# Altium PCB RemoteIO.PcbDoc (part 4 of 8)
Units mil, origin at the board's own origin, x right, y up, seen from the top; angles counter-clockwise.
Board outline 7874.02 x 2362.2 mil, 6 copper layers (Top Layer, GND1, Layer 2, PWR, GND2, Bottom Layer), stack 60.956 mil thick; 655 components, 447 nets, 2607 pads, 1444 vias.
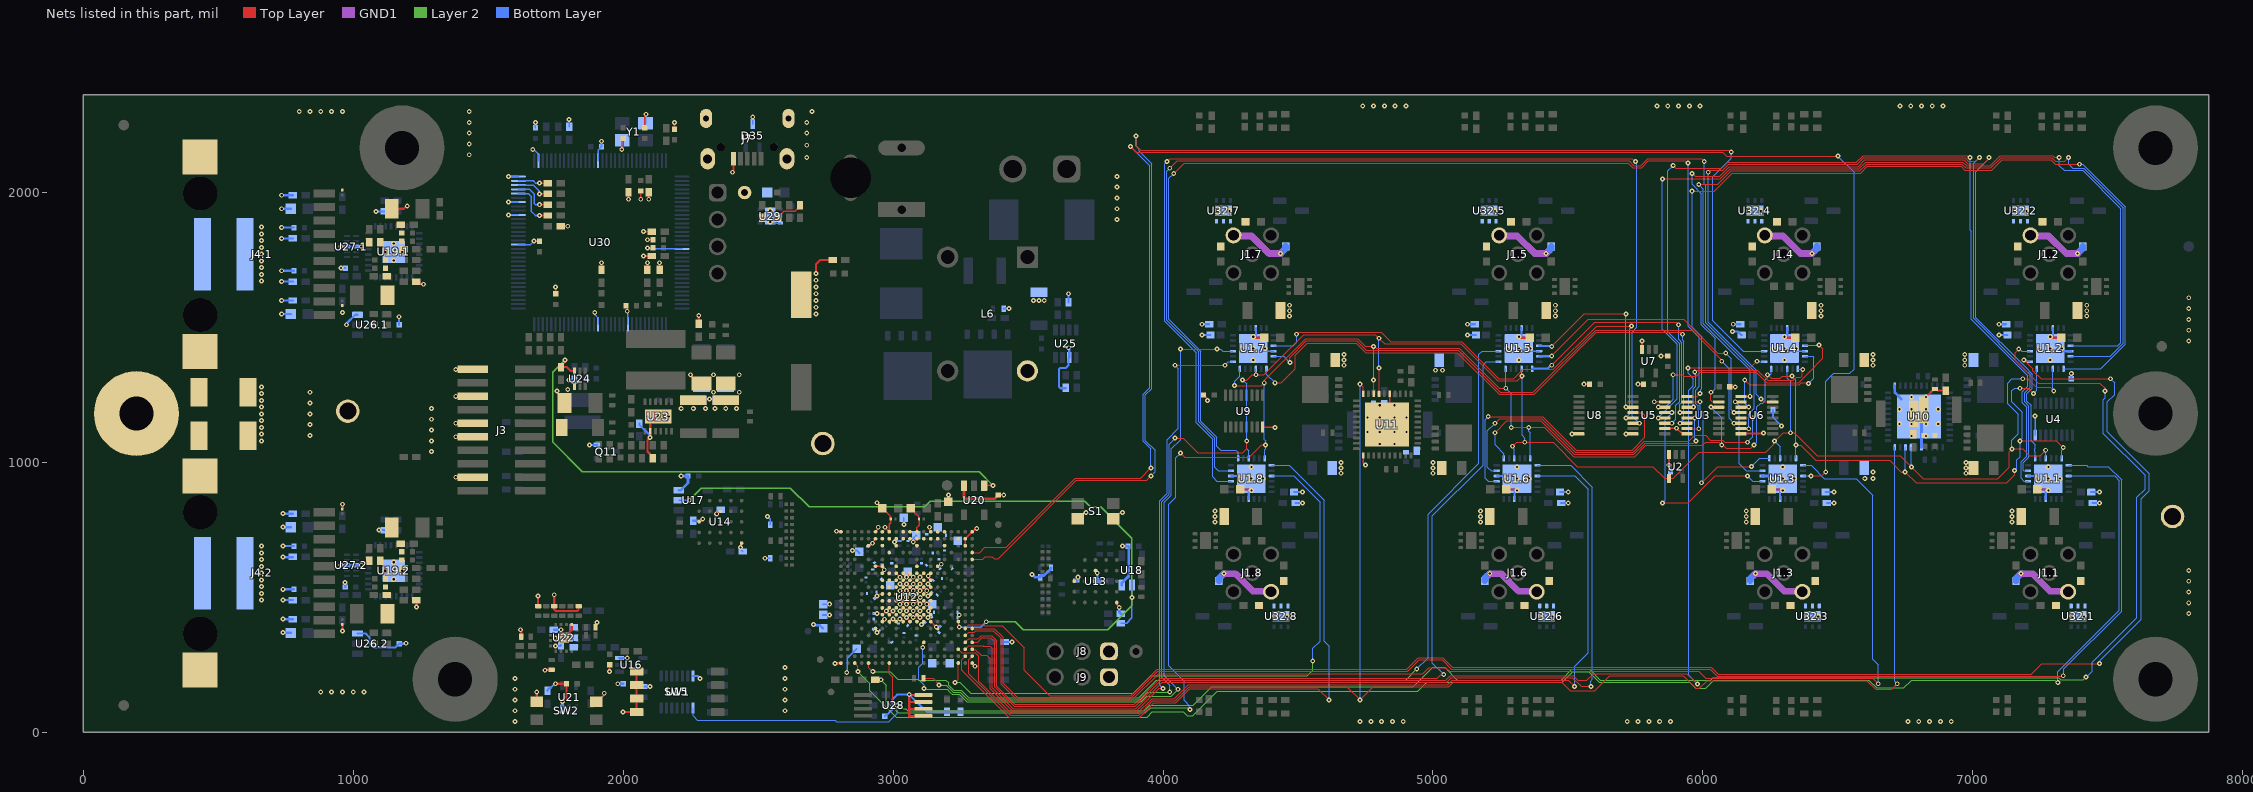
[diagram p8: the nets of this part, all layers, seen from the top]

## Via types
v1: diameter 18, hole 8, Top Layer to Bottom Layer, tented both sides, 1277 vias
v2: diameter 19.68, hole 7.87, Top Layer to Bottom Layer, tented both sides, 133 vias
v3: diameter 19.68, hole 7.87, Top Layer to Bottom Layer, 34 vias

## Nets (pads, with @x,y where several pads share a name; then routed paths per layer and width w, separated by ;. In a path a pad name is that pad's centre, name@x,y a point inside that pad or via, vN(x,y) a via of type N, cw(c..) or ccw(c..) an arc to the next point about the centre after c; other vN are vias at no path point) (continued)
\WARMRST: R113.2 U12.G3 U17.2 U18.2 | length 2932
  Top Layer w6: U12.G3@3241.93,410.43 3243.42,408.94 3243.42,391.58 v1(3245,390)
  Layer 2 w5: v1(2245,860) 2290,905 2620,905 2690,835 3117.73,835 3138.23,855.5 3709.5,855.5 3730,835 3770,835 3885,720 v1(3885,500) 3885,470 3795,380 3650,380 3649.5,379.5 3482.72,379.5 3452.22,410 v1(3345,410)
  Bottom Layer w5: U17.2@2205.87,860 v1(2245,860) ; v1(3245,390) 3325,390 v1(3345,410) ; R113.2@3843.62,405 3865,405 3885,425 v1(3885,500) U18.2@3885,545.87
CS1: U1.1.1 U12.F1 | length 5365.4
  Top Layer w4: U12.F1@3293.11,384.84 3375.16,384.84 3408,352 3408,181.63 3461.63,128 3883.25,128 3981.25,226 4906,226 4949,269 5033.63,269 5068.63,234 6027.87,234 6053.87,208 7333,208 v1(7335,210)
  Bottom Layer w4: v1(7335,210) 7337.53,212.53 7337.53,235.15 7551,448.63 7551,935.31 7501.31,985 7425.86,985 7421.65,989.21 U1.1.1@7355.3,989.21
CS2: U1.2.1 U12.F2 | length 6056.3
  Top Layer w4: U12.F2@3267.52,384.84 3280.72,398.04 3335.74,398.04 3338.79,395 3405,395 3486,314 3486,230.64 3580.64,136 3879.94,136 3977.94,234 4902.69,234 4945.69,277 5036.94,277 5071.94,242 6031.18,242 6057.18,216 7216,216 7255,255 v1(7470,255) ; v1(7189.04,1379.8) 7222.32,1346.52 7222.32,1340.6 7252.92,1310 v1(7510,1310)
  Bottom Layer w4: v1(7189.04,1379.8) 7192.83,1379.8 7196.91,1375.72 7208.91,1375.72 U1.2.1@7211.63,1372.99 ; v1(7470,255) 7471.63,256.63 7471.63,266.58 7624,418.95 7624,864.69 7654,894.69 7654,958.73 7499,1113.73 7499,1225.16 7525,1251.16 7525,1295 v1(7510,1310)
CS3: U1.3.1 U12.E2 | length 4681.6
  Top Layer w4: U12.E2@3267.52,359.25 3279.91,371.64 3301.64,371.64 3306.84,376.84 3371.84,376.84 3400,348.69 3400,178.31 3458.31,120 3886.57,120 3983.57,217 4962,217 4985,240 5047.53,240 5061.53,226 5984,226 6010,200 6630,200 v1(6650,180)
  Bottom Layer w4: U1.3.1@6371.04,989.21 6400.79,989.21 6450,940 6567.63,940 6630,877.63 6630,271.31 6650,251.31 v1(6650,180)
CS4: U1.4.1 U12.D1 | length 4484.5
  Top Layer w4: 3306,334.69 3294.14,334.69 U12.D1@3293.11,333.66 3312.82,333.66 3329.15,350 3362.37,350 3376,336.37 3376,168.37 3448.37,96 3896.51,96 3993.51,193 5048,193 5065,210 5520,210 5537,193 5570,193 5595,218 5941,218 5966,193 v1(5980,179) ; v1(5945,1350) 6175,1350 v1(6200,1375)
  Bottom Layer w4: v1(5945,1350) 5945,1330 5965,1310 5965,1285 5948,1268 5948,211 v1(5980,179) ; v1(6200,1375) 6201,1374 6226.38,1374 U1.4.1@6227.38,1372.99
CS5: U1.5.1 U12.D2 | length 3335.4
  Top Layer w4: U12.D2@3267.52,333.66 3279.91,346.05 3313.89,346.05 3325.84,358 3365.69,358 3384,339.69 3384,171.69 3451.69,104 3893.2,104 3990.2,201 5016.1,201 5028.44,213.34 5038.34,213.34 v1(5040,215)
  Bottom Layer w4: v1(5040,215) 4998.16,256.84 4998.16,801.84 5186,989.69 5186,1361 5197.99,1372.99 U1.5.1@5243.13,1372.99
CS6: U1.6.1 U12.C2 | length 3544.4
  Top Layer w4: U12.C2@3267.52,308.07 3279.91,320.46 3333.33,320.46 3333.79,320 3360,320 3368,312 3368,165.06 3445.06,88 3899.82,88 3996.82,185 5051.31,185 5068.31,202 5516.69,202 5548.69,170 v1(5585,170)
  Bottom Layer w4: U1.6.1@5386.79,989.21 5510.79,989.21 5591,909 5591,196 5585,190 v1(5585,170)
CS7: U1.7.1 U12.C1 | length 2359.3
  Top Layer w4: U12.C1@3294.98,309.94 U12.C1@3293.11,308.07 3294.98,306.2 3305.11,306.2 3326.31,285 3347.66,285 3360,272.66 3360,161.75 3441.75,80 3903.14,80 3986.14,163 v1(4000,163) ; v1(4045,1360) v1(4230,1360)
  Bottom Layer w4: v1(4000,163) 3988,175 3988,858 4015,885 4015,1085 4057,1127 4057,1348 v1(4045,1360) ; v1(4230,1360) 4230,1361.94 4241.05,1372.99 U1.7.1@4258.88,1372.99
CS8: U1.8.1 U12.B2 | length 2546
  Top Layer w4: U12.B2@3267.52,282.48 3255,269.96 3255,230 3425,60 3425.65,60 3429.65,56 3913.08,56 3966.08,109 4047.84,109 4099.84,161 4574,161 v1(4615,120)
  Bottom Layer w4: U1.8.1@4402.54,989.21 4468.41,989.21 4598,859.63 4598,337 4615,320 v1(4615,120)
DCDC_PG: R127.1 U20.1 U24.6 | length 2142.6
  Top Layer w6: R127.1@1770,1353.62 1770,1357.56 1785,1372.56 v1(1785,1380) ; U20.1@3337.4,914.13 3338.27,915 v1(3370,915)
  Top Layer w8: R127.1@1770,1353.62 1791.38,1353.62 1805.87,1339.13 U24.6@1820.32,1339.13
  Layer 2 w6: v1(1785,1380) 1739,1334 1739,1076 1849,966 3319,966 v1(3370,915)
DEBUG_ID4: R197.1 U30.63 | length 113
  Top Layer w6: v1(1690,2035) R197.1@1721.38,2035
  Bottom Layer w6: U30.63@1611.85,2043.35 1666.65,2043.35 1675,2035 v1(1690,2035)
DEBUG_ID5: R198.1 U30.62 | length 128.9
  Top Layer w6: v1(1690,1995) R198.1@1721.38,1995
  Bottom Layer w6: U30.62@1611.85,2027.6 1667.4,2027.6 1688.27,2006.73 1688.27,1996.73 v1(1690,1995)
DEBUG_ID6: R199.1 U30.61 | length 153.6
  Top Layer w6: v1(1690,1955) R199.1@1721.38,1955
  Bottom Layer w6: U30.61@1611.85,2011.85 1653.15,2011.85 1670,1995 1670,1960 1675,1955 v1(1690,1955)
DEBUG_ID7: R200.1 U30.60 | length 175.3
  Top Layer w6: v1(1690,1915) R200.1@1721.38,1915
  Bottom Layer w6: U30.60@1611.85,1996.1 1648.9,1996.1 1660,1985 1660,1930 1675,1915 v1(1690,1915)
DIN: R39.2 U1.1.24 U1.2.24 U1.3.24 U1.4.24 U1.5.24 U1.6.24 U1.7.24 U1.8.24 U3.14 U10.8 U11.8 | length 8243.9
  Top Layer w4: v1(4065,1035) 4080,1020 4320,1020 4365,1065 v1(4380,1065) ; v1(4265,1285) 4363.79,1285 4373.79,1295 v1(4375,1295) 4376.66,1296.66 4376.66,1306.56 4528.1,1458 4722,1458 4750,1430 v1(4780,1430) 4782.34,1430 4789.34,1423 5097,1423 5245,1275 v1(5270,1275) ; v1(4780,1305) 4780.39,1304.61 4780.39,1254.57 U11.8@4780.79,1254.17 ; v1(5290,1130) v1(5355,1130) 5412.63,1130 5520.84,1021.78 5748.1,1021.78 5789.31,1063 5998,1063 6010,1075 6058.79,1075 v1@6068.79,1065 ; v1(6070,1065) 6073.79,1065 6085.79,1053 6178,1053 v1(6190,1065) ; v1(6240,1325) 6252.8,1312.2 6287.2,1312.2 6295,1320 v1(6330,1320) ; v1(6345,1065) 6346.26,1063.74 6362.42,1063.74 6418.16,1008 6692,1008 6735.61,964.39 v1(6749.39,964.39) 6789.79,924 7125.21,924 7155,953.79 v1(7155,970) ; v1(7175,1080) 7310,1080 v1(7335,1055) ; v1(7175,1275) 7205,1275 v1(7225,1255)
  Top Layer w8: R39.2@2933.62,195 v1(2955,195) ; v1(6030,1205) 6030.24,1204.76 6058.82,1204.76 U3.14@6059.06,1204.53
  Layer 2 w4: v1(2955,195) 2975,175 2975,115.26 3018.26,72 3934.37,72 3954.37,92 4090.66,92 4097.66,85 v1(4100,85)
  Bottom Layer w4: v1(4065,1035) 4047,1017 4047,871.75 4021,845.75 4021,246.53 4078.34,189.18 4078.34,173.34 4078,173 4078,118.79 4097.32,99.47 4097.32,87.68 v1(4100,85) ; v1(4265,1285) 4265,1300 4284.96,1319.96 U1.7.24@4284.96,1346.91 ; v1(4375,1295) 4375,1085 4380.15,1079.85 v1@4380.15,1065 ; U1.8.24@4376.46,1015.3 4376.46,1046.46 4380,1050 v1(4380,1065) ; v1(4780,1305) v1(4780,1430) ; U1.5.24@5269.21,1346.91 5269.61,1346.52 5269.61,1275.39 v1(5270,1275) 5290,1255 v1(5290,1130) ; v1(5355,1130) 5355,1115 5360.71,1109.29 U1.6.24@5360.71,1015.3 ; v1(6030,1205) 6070,1165 v1(6070,1065) ; v1(6190,1065) 6200,1075 6200,1206.21 6213.79,1220 6221.21,1220 6232,1230.79 6232,1307 v1@6245,1320 ; v1(6240,1325) v1@6245,1320 ; U1.4.24@6253.46,1346.91 6253.46,1328.46 v1@6245,1320 ; v1(6330,1320) 6345,1305 v1(6345,1065) U1.3.24@6344.96,1015.3 ; v1(6749.39,964.39) 6750.09,965.09 6750.09,1055.13 U10.8@6750.79,1055.83 ; v1(7155,970) 7155,971.06 7163.29,979.34 7163.29,1009.35 7175,1021.06 v1(7175,1080) 7184,1089 7184,1186 7145,1225 7145,1265 7155,1275 v1(7175,1275) ; v1(7225,1255) 7237.72,1267.72 U1.2.24@7237.72,1346.91 ; U1.1.24@7329.21,1015.3 7329.21,1045.42 7335,1051.21 v1(7335,1055)
DIO_EN1: U1.1.19 U3.15 | length 3299.3
  Top Layer w4: v1(5960,2070) 5961.21,2070 5971.21,2060 6062.63,2060 6098.63,2096 6574.94,2096 6599.94,2121 6966.47,2121 6980.47,2107 7040.79,2107 v1@7061.01,2127.22 ; v1(6030,1260) 6030,1230 6034.73,1225.27 6058,1225.27 U3.15@6059.06,1224.21
  Bottom Layer w4: v1(5960,2070) 5960,2030 5994,1996 5994,1510.9 6045,1459.9 6045,1272.5 6032.5,1260 v1(6030,1260) ; v1@7060.81,2127.02 7011,2077.21 7011,1536.63 7191.63,1356 7220,1327.63 7220,1275 7200,1255 7200,1227.63 7216,1211.63 7216,1079.82 7230.47,1065.34 7230.47,1051.69 7230,1051.21 7230,1038.79 7230.79,1038 U1.1.19@7230.79,1015.3
  other v1: 7060,2130
DIO_EN2: U1.2.19 U3.1 | length 3332.6
  Top Layer w4: U3.1@5940.94,1243.9 5977.06,1243.9 5988.16,1255 v1(5990,1255) ; v1(5960,2005) 6041.57,2005 6108.57,2072 6584.88,2072 6609.88,2097 6956.53,2097 6970.53,2083 7070.63,2083 7108.63,2121 7289,2121 7305,2105 v1(7395,2105)
  Bottom Layer w4: v1(5960,2005) 5960,1501.31 5995,1466.31 5995,1273.69 5991.31,1270 5991.31,1256.31 v1(5990,1255) ; U1.2.19@7336.14,1346.91 7474.28,1346.91 7565,1437.63 7565,1946.66 7407.44,2104.23 7395.77,2104.23 v1(7395,2105)
DIO_EN3: U1.3.19 U3.2 | length 646.2
  Top Layer w4: U3.2@5940.94,1224.21 5941.34,1224.61 5989.61,1224.61 v1(5990,1225) ; v1(5995,925) 6055,985 v1(6180,985)
  Bottom Layer w4: v1(5990,1225) 5990,1195.32 6002,1183.32 6002,934.34 5995,927.34 v1(5995,925) ; v1(6180,985) 6210.3,1015.3 U1.3.19@6246.54,1015.3
DIO_EN4: U1.4.19 U3.3 | length 626.3
  Top Layer w4: U3.3@5940.94,1204.53 5941.42,1205 v1(5965,1205) ; v1(5970,1335) 5972.34,1335 5979.34,1342 6201.79,1342 6239.58,1304.21 6335.42,1304.21 6346.21,1315 6362.37,1315 6367.32,1319.95 6367.32,1342.32 v1(6370,1345)
  Bottom Layer w4: v1(5965,1205) 5965,1273.69 5973,1281.69 5973,1325.66 5972.68,1325.98 5972.68,1332.32 v1(5970,1335) ; U1.4.19@6351.89,1346.91 6353.8,1345 v1(6370,1345)
DIO_EN5: U1.5.19 U3.4 | length 978.3
  Top Layer w4: v1(5440,1360) 5600,1520 5902.1,1520 5910,1512.1 v1(5910,1510) ; v1(5915,1185) 5915.08,1184.92 5940.87,1184.92 U3.4@5940.94,1184.84
  Bottom Layer w4: v1(5910,1510) 5910,1455.81 5922,1443.81 5922,1222 5915,1215 v1(5915,1185)
  Bottom Layer w8: U1.5.19@5367.64,1346.91 5424.2,1346.91 5437.29,1360 v1(5440,1360)
DIO_EN6: U1.6.19 U3.5 | length 1059.7
  Top Layer w4: v1(5230,1110) 5274,1154 5399.94,1154 5524.16,1029.78 5744.78,1029.78 5786,1071 5966,1071 v1(5975,1080) ; U3.5@5940.94,1165.16 5941.02,1165.08 5969.92,1165.08 v1(5970,1165)
  Bottom Layer w4: v1(5230,1110) 5230,1065 5262.28,1032.72 U1.6.19@5262.28,1015.3 ; v1(5970,1165) 5970,1088.79 5975,1083.79 v1(5975,1080)
DIO_EN7: U1.7.19 U3.6 | length 2206.3
  Top Layer w4: v1(4415,1295) 4437.37,1295 4490,1347.63 4490,1397.27 4534.73,1442 4715.37,1442 4750.37,1407 5090.37,1407 5245.37,1252 5375.84,1252 5605.84,1482 5915.66,1482 5922.66,1475 v1(5925,1475) ; v1(5915,1145) 5915.24,1145.24 5940.71,1145.24 U3.6@5940.94,1145.47
  Bottom Layer w4: U1.7.19@4383.39,1346.91 4383.39,1326.61 v1(4415,1295) ; v1(5915,1145) 5930,1160 5930,1447.13 5925,1452.13 v1(5925,1475)
DIO_EN8: U1.8.19 U3.7 | length 4199.4
  Top Layer w4: v1(4040,2070) 4079,2109 5723.47,2109 5740.47,2092 5773.31,2092 5798.31,2117 5935.66,2117 5942.66,2110 v1(5945,2110) ; U3.7@5940.94,1125.79 5941.34,1125.39 5984.61,1125.39 v1(5985,1125)
  Bottom Layer w4: v1(4040,2070) 4022,2052 4022,1530.63 4140,1412.63 4140,1153.33 4199.84,1093.48 4199.84,1060.16 4214.84,1045.16 4269.84,1045.16 4277.98,1037.02 U1.8.19@4278.03,1015.3 ; v1(5945,2110) 5945,1505 5987,1463 5987,1282 5973,1268 5973,1218.21 5982,1209.21 5982,1192 5985,1189 v1(5985,1125)
DIO_RX1: U1.1.15 U5.11 | length 3477.4
  Top Layer w4: U5.11@5859.06,1145.47 5859.29,1145.24 5884.76,1145.24 v1(5885,1145) ; v1(5890,2100) 5900,2090 6070,2090 6092,2112 6568.31,2112 6593.31,2137 6980.66,2137 6987.66,2130 v1(6990,2130)
  Bottom Layer w4: v1(5885,1145) 5900,1160 5900,1211.31 5914,1225.31 5914,1440.5 5870,1484.5 5870,2080 v1(5890,2100) ; v1(6990,2130) 6990,1860 6995,1855 6995,1530 7204,1321 7204,1281.63 7184,1261.63 7184,1221 7200,1205 7200,1023.43 7179.29,1002.72 7179.29,940.71 7189.63,930.37 7204.49,930.37 U1.1.15@7204.7,930.16
DIO_RX2: U1.2.15 U5.12 | length 3495.1
  Top Layer w4: v1(5835,1165) 5858.9,1165 U5.12@5859.06,1165.16 ; v1(5850,2050) 5851.21,2051.21 6065.15,2051.21 6101.94,2088 6578.25,2088 6603.25,2113 6963.16,2113 6977.16,2099 7064,2099 7102,2137 7295.63,2137 7302.63,2130 v1(7320,2130)
  Bottom Layer w4: v1(5835,1165) 5906,1236 5906,1437.19 5850,1493.19 v1(5850,2050) ; v1(7320,2130) 7320,2100 7338,2082 7407.04,2082 7549,1940.04 7549,1444.25 7536.79,1432.05 U1.2.15@7362.22,1432.05
DIO_RX3: U1.3.15 U5.13 | length 795.6
  Top Layer w4: v1(5850,850) 5945,850 6045,950 v1(6165,950) ; U5.13@5859.06,1184.84 5884.84,1184.84 v1(5885,1185)
  Bottom Layer w4: v1(5850,850) 5860,860 5860,1157.47 5878,1175.47 5878,1175.66 5885,1182.66 v1(5885,1185) ; v1(6165,950) 6184.84,930.16 U1.3.15@6220.45,930.16
DIO_RX4: U1.4.15 U5.14 | length 905.1
  Top Layer w4: v1(5835,1205) 5835.47,1204.53 U5.14@5859.06,1204.53 ; v1(5890,1325) 5925,1325 5930,1320 5976.21,1320 5985,1328.79 5990.21,1334 6198.47,1334 6236.27,1296.21 6354.89,1296.21 6393.69,1335 6444.34,1385.66 6444.34,1420.66 v1(6430,1435)
  Bottom Layer w4: v1(5835,1205) 5860,1205 5890,1235 v1(5890,1325) ; U1.4.15@6377.97,1432.05 6379.45,1433.52 6428.52,1433.52 v1(6430,1435)
DIO_RX5: U1.5.15 U5.3 | length 743
  Top Layer w4: v1(5440,1430) 5560,1550 v1(5715,1550) ; v1(5715,1205) 5715.24,1204.76 5740.71,1204.76 U5.3@5740.94,1204.53
  Bottom Layer w4: v1(5715,1205) v1(5715,1550)
  Bottom Layer w8: U1.5.15@5393.72,1432.05 5394.44,1431.32 5438.68,1431.32 v1(5440,1430)
DIO_RX6: U1.6.15 U5.4 | length 1061.6
  Top Layer w4: v1(5205,1170) 5406.57,1170 5530.78,1045.78 5630.63,1045.78 5630.85,1046 5738.37,1046 5785,1092.63 5785,1175 5775.16,1184.84 U5.4@5740.94,1184.84
  Bottom Layer w4: v1(5205,1170) 5194,1159 5194,941 5204.84,930.16 U1.6.15@5236.2,930.16
DIO_RX7: U1.7.15 U5.5 | length 1890.1
  Top Layer w4: v1(4495,1475) 4497.34,1475 4504.34,1482 4808,1482 4843,1447 5106.94,1447 5243.94,1310 5298.79,1310 5333.79,1345 5446.21,1345 5606.21,1505 v1(5735,1505) ; v1(5715,1165) 5715.08,1165.08 5740.87,1165.08 U5.5@5740.94,1165.16
  Bottom Layer w4: U1.7.15@4409.47,1432.05 4482.05,1432.05 4495,1445 v1(4495,1475) ; v1(5715,1165) 5730,1180 5730,1496.21 5735,1501.21 v1(5735,1505)
DIO_RX8: U1.8.15 U5.6 | length 4073.6
  Top Layer w4: v1(4015,2115) 4025,2125 5737.66,2125 5747.66,2115 v1(5750,2115) ; U5.6@5740.94,1145.47 5764.53,1145.47 v1(5765,1145)
  Bottom Layer w4: v1(4015,2115) 4014.9,2115 4006,2106.1 4006,1524 4124,1406 4124,1146.7 4183.84,1086.86 4183.84,946.16 4199.84,930.16 U1.8.15@4251.95,930.16 ; v1@5755,2111.79 5755,1500 5738,1483 5738,1172 v1(5765,1145)
DIO_TX1: U1.1.17 U6.15 | length 3304.4
  Top Layer w4: v1(6020,2075) 6022.34,2075 6029.34,2082 6073.31,2082 6095.31,2104 6571.63,2104 6596.63,2129 6969.79,2129 6983.79,2115 7010,2115 v1(7025,2130) ; v1(6215,1235) 6225.79,1224.21 U6.15@6259.06,1224.21
  Bottom Layer w4: v1(6020,2075) 6020,1518.84 6198,1340.84 6198,1252 v1(6215,1235) ; v1(7025,2130) 7003,2108 7003,1533.31 7188.31,1348 7212,1324.31 7212,1278.31 7192,1258.31 7192,1224.31 7208,1208.31 7208,1020.12 7187.29,999.41 7187.29,971.87 7189.63,969.53 U1.1.17@7204.7,969.53
DIO_TX2: U1.2.17 U6.1 | length 3344
  Top Layer w4: v1(5985,2030) 6055.25,2030 6105.25,2080 6581.57,2080 6606.57,2105 6959.85,2105 6973.85,2091 7067.31,2091 7105.31,2129 7292.31,2129 7306.31,2115 7340,2115 v1(7355,2130) ; U6.1@6140.94,1243.9 6141.5,1244.45 6174.45,1244.45 v1(6175,1245)
  Bottom Layer w4: v1(5985,2030) 6002,2013 6002,1514.21 6096.21,1420 6175,1341.21 v1(6175,1245) ; v1(7355,2130) 7355,2105 7370,2090 7410.35,2090 7557,1943.35 7557,1440.94 7508.74,1392.68 U1.2.17@7362.22,1392.68
DIO_TX3: U1.3.17 U6.2 | length 353.5
  Top Layer w4: v1(6120,1225) 6120.79,1224.21 U6.2@6140.94,1224.21
  Bottom Layer w4: v1(6120,1225) 6134.61,1210.39 6134.61,995.39 6160.47,969.53 U1.3.17@6220.45,969.53
DIO_TX4: U1.4.17 U6.3 | length 516.5
  Top Layer w4: U6.3@6140.94,1204.53 6141.18,1204.76 6169.76,1204.76 v1(6170,1205) ; v1(6155,1305) 6173,1287 6357,1287 6365,1295 v1@6386.14,1295
  Bottom Layer w4: v1(6155,1305) 6155,1220 v1(6170,1205) ; U1.4.17@6377.97,1392.68 6408.65,1392.68 6410.99,1390.33 6410.99,1312.21 v1(6391.89,1293.11)
DIO_TX5: U1.5.17 U6.4 | length 1058.4
  Top Layer w4: v1(5440,1395) 5575,1530 5930,1530 6055,1405 v1(6085,1405) ; v1(6115,1185) 6115.08,1184.92 6140.87,1184.92 U6.4@6140.94,1184.84
  Bottom Layer w4: v1(6085,1405) 6105,1385 6105,1195 v1(6115,1185)
  Bottom Layer w8: U1.5.17@5393.72,1392.68 5394.44,1393.4 5438.4,1393.4 v1(5440,1395)
DIO_TX6: U1.6.17 U6.5 | length 1385.4
  Top Layer w4: v1(5230,1145) 5247,1162 5403.25,1162 5527.47,1037.78 5633.94,1037.78 5634.16,1038 5741.69,1038 5782.69,1079 5948.61,1079 5969.61,1100 6010,1100 6027,1083 6073.21,1083 6081.21,1075 v1(6165,1075) ; U6.5@6140.94,1165.16 6184.84,1165.16 v1(6185,1165)
  Bottom Layer w4: v1(5230,1145) 5202,1117 5202,983 5215.47,969.53 U1.6.17@5236.2,969.53 ; v1(6165,1075) 6185,1095 v1(6185,1165)
DIO_TX7: U1.7.17 U6.6 | length 2214.8
  Top Layer w4: v1(4470,1370) 4470,1388.59 4531.41,1450 4718.69,1450 4753.69,1415 5093.69,1415 5248.69,1260 5372.53,1260 5602.53,1490 5958.69,1490 6070,1378.69 v1(6070,1375) ; v1(6115,1145) 6115.24,1145.24 6140.71,1145.24 U6.6@6140.94,1145.47
  Bottom Layer w4: U1.7.17@4409.47,1392.68 4447.32,1392.68 v1(4470,1370) ; v1(6070,1375) 6097,1348 6097,1163 v1(6115,1145) v1@6116.61,1146.61
DIO_TX8: U1.8.17 U6.7 | length 4367.8
  Top Layer w4: v1(4025,2090) 4052,2117 5726.79,2117 5743.79,2100 5770,2100 5795,2125 5995,2125 v1(6005,2115) ; U6.7@6140.94,1125.79 6141.34,1125.39 6169.61,1125.39 v1(6170,1125)
  Bottom Layer w4: v1(4025,2090) 4014,2079 4014,1527.31 4132,1409.31 4132,1150.01 4191.84,1090.17 4191.84,983.16 4205.47,969.53 U1.8.17@4251.95,969.53 ; v1(6005,2115) 6005,2031.21 6010,2026.21 6010,1517.53 6190,1337.53 6190,1200 6170,1180 v1(6170,1125)
DOUT: R35.1 U1.1.21 U1.2.21 U1.3.21 U1.4.21 U1.5.21 U1.6.21 U1.7.21 U1.8.21 U2.4 U10.7 U11.7 | length 7541.7
  Top Layer w4: R35.1@3112.72,200 3148.69,200 3170,178.69 v1(3170,175) ; v1(4045,1090) 4075,1090 4129,1036 4296,1036 4310,1050 v1(4310,1080) ; v1(4295,1305) 4310,1305 4330,1325 v1(4345,1325) 4372.47,1325 4521.47,1474 4786,1474 v1(4800,1460) 4821,1439 5103.63,1439 5240.63,1302 5312,1302 v1(5330,1320) ; v1(4800,1350) 4800.24,1349.76 4800.24,1254.41 U11.7@4800.47,1254.17 ; v1(5295,1060) 5310,1075 v1(5340,1075) 5445,1075 5535,985 5815,985 5859.29,940.71 U2.4@5874.41,940.71 5890.71,940.71 5987,1037 6233.21,1037 6263.39,1067.18 6263.39,1078.39 v1(6265,1080) 6268.41,1080 6298.41,1110 v1(6325,1110) 6338.79,1110 6423.79,1025 6731.21,1025 6770,986.21 6770,985 6771.89,983.11 v1(6773.11,983.11) 6816.21,940 7092.47,940 7135,982.53 7135,1040 v1(7145,1050) 7185,1050 7210,1025 7250,1025 v1(7270,1045) ; v1(7185,1310) 7203.69,1310 7235.69,1278 7287,1278 v1(7300,1265)
  Layer 2 w4: v1(3170,175) 3196.66,175 3199,172.66 3199,172.16 3222.16,149 3249.18,149 3277.18,121 3915.49,121 3942.49,148 4023,148 v1(4025,150)
  Bottom Layer w4: v1(4025,150) 4025,175 3996,204 3996,854.69 4023,881.69 4023,1068 v1(4045,1090) ; v1(4295,1305) 4296.21,1305 4310,1291.21 v1(4310,1080) 4310,1050 4317.4,1042.6 U1.8.21@4317.4,1015.3 ; U1.7.21@4344.02,1346.91 4344.51,1346.42 4344.51,1325.49 v1(4345,1325) ; v1(4800,1350) v1(4800,1460) ; v1(5295,1060) 5295,1056.21 5301.65,1049.56 U1.6.21@5301.65,1015.3 ; U1.5.21@5328.27,1346.91 5329.13,1346.04 5329.13,1320.87 v1(5330,1320) 5330,1100 5340,1090 v1(5340,1075) ; v1(6265,1080) 6285.91,1059.09 U1.3.21@6285.91,1015.3 ; U1.4.21@6312.52,1346.91 6312.52,1312.48 6325,1300 v1(6325,1110) ; U10.7@6770.47,1055.83 6771.79,1054.51 6771.79,984.42 v1(6773.11,983.11) ; v1(7145,1050) 7145,1082.53 7168,1105.53 7168,1179.37 7129,1218.37 7129,1294 7145,1310 v1(7185,1310) ; v1(7270,1045) 7270.08,1044.92 7270.08,1015.37 U1.1.21@7270.16,1015.3 ; U1.2.21@7296.77,1346.91 7296.77,1272.02 7300,1268.79 v1(7300,1265)
EARTH: C140.1.2 C140.2.2 H2.1 J4.1.Shell J4.2.Shell R193.1.1 R193.2.1
GND: C1.1.1 C1.2.1 C1.3.1 C1.4.1 C1.5.1 C1.6.1 C1.7.1 C1.8.1 C2.1.1 C2.2.1 C2.3.1 C2.4.1 C2.5.1 C2.6.1 C2.7.1 C2.8.1 C3.1 C4.1 C5.1 C6.1 C7.1 C8.1 C9.1 C10.1 C11.1 C12.1 C13.1 C14.1 C15.1 C16.1 C17.1 C18.1 C19.1 C20.1 C21.1 C22.1 C23.1 C24.1 C25.2 C26.2 C27.2 C28.2 C29.2 C30.1 C31.1 C32.2 C33.1 C34.1 C35.2 C36.1 C37.1 C38.1 C39.2 C41.2 C42.2 C43.2 C44.1 C45.1 C46.1 C47.1 C48.1 C49.1 C50.1 C51.1 C52.1 C53.1 C54.1 C55.1 C56.1 C57.1 C58.1 C59.1 C60.1 C61.1 C62.1 C63.1 C64.1 C65.1 C66.1 C67.1 C68.1 C69.1 C70.1 C71.1 C72.1 C73.1 C74.1 C75.1 C76.1 C77.1 C78.1 C79.1 C80.1 C81.1 C82.1 C83.1 C84.1 C85.1 C86.1 C87.1 C88.1 C89.1 C90.1 C91.1 C92.1 C93.1 C94.1 C95.1 C96.1 C97.1 C98.1 C99.1 C100.1 C101.1 C102.1 C104.1 C105.1 C106.1 C107.1 C108.2 C109.2 C110.2 C111.2 C113.2 C115.2 C116.2 C118.1 C119.1 C121.1 C122.1 C123.1 C124.1 C125.1 C126.1 C127.1.2 C127.2.2 C128.1.1 C128.2.1 C129.1.2 C129.2.2 C130.1.2 C130.2.2 C131.1.1 C131.2.1 C132.1.2 C132.2.2 C133.1.2 C133.2.2 C134.1.1 C134.2.1 C135.1.1 C135.2.1 C136.1.2 C136.2.2 C137.1.1 C137.2.1 C138.1.2 C138.2.2 C139.1.1 C139.2.1 C140.1.1 C140.2.1 C141.1.1 C141.2.1 C142.1.1 C142.2.1 C143.1 C144.2 C146.2 C147.1 C148.1 C149.1 C150.1 C151.1 C152.1 C153.1 C154.2 C155.2 C156.1 C157.1 C158.2 C159.2 C160.1 C161.1 C162.1 C163.1 C164.2 D26.1.2 D26.2.2 D27.1.2 D27.2.2 D35.3 J1.1.3 J1.2.3 J1.3.3 J1.4.3 J1.5.3 J1.6.3 J1.7.3 J1.8.3 J3.4 J3.10 J3.12 J3.16 J3.20 J7.5 J7.Z1 J7.Z2 J7.Z3 J7.Z4 J8.1 J9.1 L6.4 Q11.2 R1.1.1 R1.2.1 R1.3.1 R1.4.1 R1.5.1 R1.6.1 R1.7.1 R1.8.1 R2.1.1 R2.2.1 R2.3.1 R2.4.1 R2.5.1 R2.6.1 R2.7.1 R2.8.1 R30.2 R31.1 R32.1 R36.1 R37.2 R38.1 R61.1 R62.1 R83.1 R84.1 R105.1 R106.1 R107.1 R108.1 R111.1 R112.1 R124.1 R128.1 R132.1 R133.1 R135.1 R136.1 R138.1 R142.1 R143.1 R144.1 R163.1.1 R163.2.1 R176.1.1 R176.2.1 R177.1.1 R177.2.1 R178.1.1 R178.2.1 R181.1.1 R181.2.1 R182.1.1 R182.2.1 R191.1.1 R191.2.1 R192.1.1 R192.2.1 R193.1.2 R193.2.2 R195.1 R196.1 R206.1 R207.1 R209.2 R210.1 R213.1 RV3.1.1 RV3.2.1 RV3.3.1 RV3.4.1 RV3.5.1 RV3.6.1 RV3.7.1 RV3.8.1 RV4.1.1 RV4.2.1 RV4.3.1 RV4.4.1 RV4.5.1 RV4.6.1 RV4.7.1 RV4.8.1 RV6.1.2 RV6.2.2 RV6.3.2 RV6.4.2 RV6.5.2 RV6.6.2 RV6.7.2 RV6.8.2 S1.2 S1.4 SW1.1 SW1.2 SW1.3 SW1.4 SW2.1 SW2.3 TP3.1 TP4.1 TP5.1 TP9.1 U1.1.10 U1.1.16 U1.1.25 U1.2.10 U1.2.16 U1.2.25 U1.3.10 U1.3.16 U1.3.25 U1.4.10 U1.4.16 U1.4.25 U1.5.10 U1.5.16 U1.5.25 U1.6.10 U1.6.16 U1.6.25 U1.7.10 U1.7.16 U1.7.25 U1.8.10 U1.8.16 U1.8.25 U2.3 U3.8 U4.8 U5.8 U5.10 U5.15 U6.8 U7.3 U8.8 U9.8 U10.5 U10.21 U10.41 U11.5 U11.21 U11.41 U12.A1 U12.A20 U12.F6 U12.F15 U12.G7 U12.G8 U12.G9 U12.G10 U12.G11 U12.G12 U12.G13 U12.G14 U12.H7 U12.H8 U12.H9 U12.H10 U12.H11 U12.H12 U12.H13 U12.H14 U12.J7 U12.J8 U12.J9 U12.J10 U12.J11 U12.J12 U12.J13 U12.J14 U12.K7 U12.K8 U12.K9 U12.K10 U12.K11 U12.K12 U12.K13 U12.K14 U12.L7 U12.L8 U12.L9 U12.L10 U12.L11 U12.L12 U12.L13 U12.L14 U12.M7 U12.M8 U12.M9 U12.M10 U12.M11 U12.M12 U12.M13 U12.M14 U12.N7 U12.N8 U12.N9 U12.N10 U12.N11 U12.N12 U12.N13 U12.N14 U12.P7 U12.P8 U12.P9 U12.P10 U12.P11 U12.P12 U12.P13 U12.P14 U12.R6 U12.R9 U12.R12 U12.R14 U12.R15 U12.U13 U12.V2 U12.V5 U12.V9 U12.V12 U12.V14 U12.V16 U12.W2 U12.W3 U12.W6 U12.W7 U12.W8 U12.W9 U12.W10 U12.W11 U12.W12 U12.W13 U12.W14 U12.W15 U12.Y1 U12.Y5 U12.Y6 U12.Y7 U12.Y9 U12.Y10 U12.Y11 U12.Y13 U12.Y14 U12.Y15 U12.Y20 U13.B3 U13.C1 U13.E5 U14.B3 U14.C1 U14.E5 U15.7 U16.3 U17.3 U18.3 U19.1.33 U19.2.33 U20.3 U21.3 U22.1 U22.17 U23.8 U23.13 U24.1 U25.2 U26.1.3 U26.2.3 U27.1.3@977.13,1800 U27.1.8@1010,1800 U27.2.3@977.13,618.9 U27.2.8@1010,618.9 U28.1 U28.2 U28.3 U28.4 U29.3 U29.7@2545,1912.28 U30.10 U30.17 U30.48 U30.55 U30.58 U30.64 U30.66 U30.80 U30.114 U32.1.1 U32.1.2 U32.1.3 U32.1.7@7390,430 U32.2.1 U32.2.2 U32.2.3 U32.2.7@7176.93,1932.2 U32.3.1 U32.3.2 U32.3.3 U32.3.7@6405.75,430 U32.4.1 U32.4.2 U32.4.3 U32.4.7@6192.68,1932.2 U32.5.1 U32.5.2 U32.5.3 U32.5.7@5208.43,1932.2 U32.6.1 U32.6.2 U32.6.3 U32.6.7@5421.5,430 U32.7.1 U32.7.2 U32.7.3 U32.7.7@4224.17,1932.2 U32.8.1 U32.8.2 U32.8.3 U32.8.7@4437.24,430 Y1.2 Y1.4 | length 12651
  Top Layer w6: v1(1670,1820) 1689.69,1820 C153.1@1690,1819.68 ; C152.1@1750,1624.68 v1(1750,1650) ; R210.1@1768.62,1875 v1(1795,1875) ; R195.1@1920,1713.62 v1(1920,1740) ; v1(1995,2160) 1995,2163.25 2000,2168.25 C160.1@2000,2200.32 ; C151.1@2010.32,1580 2015,1575.32 v1(2015,1560) ; v1(2020,1975) C158.2@2020,2001.38 ; v1(2065,1975) C149.1@2065,2005.32 ; v1(2075,1765) C159.2@2106.38,1765 ; v1(2075,1855) C155.2@2106.38,1855 ; C161.1@2080,2239.68 2080,2281.75 2085,2286.75 v1(2085,2290) ; R207.1@2090,1713.62 v1(2090,1740) ; v1(2090,1795) C157.1@2110.32,1795 ; v1(2090,1825) C156.1@2110.32,1825 ; v1(2095,1975) C154.2@2095,2001.38 ; R206.1@2135,1713.62 v1(2135,1740) ; C147.1@2190,2234.68 v1(2190,2260) ; U14.C1@2281.26,780 2283.13,780 2293.13,790 v1(2295,790) ; v1(2346.49,809.68) 2348.4,809.68 2358.09,819.37 U14.B3@2360,819.37 U14.B3@2360,817.37 ; v1@2437.33,690.57 2437.33,699.85 U14.E5@2438.74,701.26 ; C146.2@2575,1906.38 2575,1910.32 2594.68,1930 2635.32,1930 2655,1949.68 R196.1@2655,1953.62 ; U12.V16@2909.25,691.93 2911.36,691.93 2920.34,700.91 v1(2923.51,700.91) ; v1@2925,700 2925,705.57 2934.84,715.41 U12.W15@2934.84,717.52 ; U12.F15@2934.84,384.84 2936.33,383.35 2936.33,376.92 2940,373.25 v1(2940,370) ; U12.R15@2934.84,615.16 U12.R14@2960.43,615.16 ; v1(2940,505) 2943.25,505 2949.55,511.31 2958.94,511.31 U12.L14@2960.43,512.8 ; v1(2940,850.5) C125.1@2960.47,830 2981.71,808.76 2990.52,799.95 2990.52,790.82 C126.1@2991.34,790 2991.34,776.34 2986.02,771.02 U12.Y13@2986.02,743.11 ; U12.G14@2960.43,410.43 2960.43,410.75 2968.57,418.9 v1(2968.57,419.22) ; U12.H14@2960.43,436.02 2960.73,436.02 2974.7,450 v1(2975,450) ; U12.V14@2960.43,691.93 U12.V14@2961.18,691.93 ; U12.W14@2960.43,717.52 U12.W14@2961.46,717.52 ; v1(2970,760) 2975,755 2975,754.13 U12.Y13@2986.02,743.11 ; U12.G13@2986.02,410.43 2988.13,410.43 2997.7,420 v1(3000,420) ; U12.H13@2986.02,436.02 v1(3000,450) ; U12.Y13@2986.02,742.07 U12.Y13@2986.02,743.11 ; U12.P12@3011.61,589.57 3011.61,589.17 3025.55,575.23 v1(3025.55,574.83) ; U12.W12@3011.61,717.07 U12.W12@3011.61,717.52 ; v1(3025,420) 3026.32,420 3035.89,410.43 U12.G11@3037.2,410.43 ; v1(3025.55,474.83) 3025.55,475.19 3037.2,486.84 U12.K11@3037.2,487.2 ; v1(3025.55,524.83) 3025.55,525.78 3037.2,537.43 U12.M11@3037.2,538.39 ; v1(3026.22,450) 3026.22,450.32 3037.2,461.3 U12.J11@3037.2,461.61 ; v1(3026.22,500) 3026.22,500.91 3037.2,511.89 U12.L11@3037.2,512.8 ; v1(3026.22,550) 3026.22,551.5 3037.2,562.48 U12.N11@3037.2,563.98 ; v1(3050,425) 3050,424.11 3062.8,411.32 U12.G10@3062.8,410.43 ; v1(3050,450) 3050.59,450 3062.2,461.61 U12.J10@3062.8,461.61 ; v1(3050,475) 3050.3,475 3062.5,487.2 U12.K10@3062.8,487.2 ; v1(3050,500) U12.L10@3062.8,512.8 ; v1(3050,525) 3050,525.3 3062.8,538.09 U12.M10@3062.8,538.39 ; v1(3050,550) 3050,550.59 3062.8,563.39 U12.N10@3062.8,563.98 ; v1(3050,575) 3050,575.89 3062.8,588.68 U12.P10@3062.8,589.57 ; C123.1@3065.47,830 3095.52,799.95 3095.52,790.82 C124.1@3096.34,790 3096.34,766.34 3095,765 ; v1(3075,425) 3076.18,425 3087.2,436.02 U12.H9@3088.39,436.02 ; v1(3075,450) 3075.89,450 3087.5,461.61 U12.J9@3088.39,461.61 ; v1(3075,475) 3075.59,475 3087.8,487.2 U12.K9@3088.39,487.2 ; v1(3075,500) 3075.3,500 3088.09,512.8 U12.L9@3088.39,512.8 ; v1(3075,525) U12.M9@3088.39,538.39 ; v1(3075,550) 3075,550.59 U12.N9@3088.39,563.98 ; v1(3075,575) 3075,575.59 3088.39,588.98 U12.P9@3088.39,589.57 ; v1(3075,705) 3075.43,705 3087.95,717.52 U12.W9@3088.39,717.52 ; U12.Y9@3088.39,743.11 3088.39,759.3 3094.54,765.46 ; v1(3100,425) 3101.48,425 3112.5,436.02 U12.H8@3113.98,436.02 ; v1(3100,450) 3101.18,450 3112.8,461.61 U12.J8@3113.98,461.61 ; v1(3100,475) 3100.89,475 3113.09,487.2 U12.K8@3113.98,487.2 ; v1(3100,525) 3100.46,525 3113.84,538.39 U12.M8@3113.98,538.39 ; v1(3100,550) U12.N8@3113.98,563.98 ; v1(3100,575) 3100,575.3 3113.98,589.27 U12.P8@3113.98,589.57 ; v1(3100.59,500) 3113.39,512.8 U12.L8@3113.98,512.8 ; v1(3105,400) 3105,400.73 3113.98,409.7 U12.G8@3113.98,410.43 ; v1(3125,475) 3126.18,475 3138.39,487.2 U12.K7@3139.57,487.2 ; v1(3125,525) v1@3130,530 ; v1(3130,425) 3130,425.73 3139.57,435.3 U12.H7@3139.57,436.02 ; v1(3130,505) 3130.89,505 3138.68,512.8 U12.L7@3139.57,512.8 ; v1(3130,550) 3130,548.98 3139.57,539.41 U12.M7@3139.57,538.39 ; v1(3130.25,579.93) 3132.54,577.64 3132.54,573.11 3139.57,566.08 U12.N7@3139.57,563.98 ; v1(3130.75,450) 3130.75,451.4 3139.57,460.22 U12.J7@3139.57,461.61 ; U12.G7@3139.57,410.43 v1(3160,390) U12.F6@3165.16,384.84 ; U12.R6@3165.16,615.16 3167.26,615.16 3172.48,620.37 3176.11,620.37 v1(3178.41,622.67) ; C121.1@3205,854.53 v1(3205,880) ; U12.V2@3267.52,691.93 U12.W2@3267.52,717.52 U12.Y1@3293.11,743.11 U12.Y1@3295,745 ; C37.1@3389.69,880 C37.1@3390,879.68 3409.68,879.68 v1(3410,880) ; U13.C1@3671.26,560 3671.26,560.63 3685,574.37 v1(3685,575) ; S1.2@3684.06,791.46 3686.02,791.46 3707.27,812.7 3712.7,812.7 v1(3715,815) ; U13.B3@3752.11,599.37 U13.B3@3750,599.37 3750,597.92 3756.6,591.32 v1(3756.6,589.87) ; S1.4@3815.94,791.46 3817.91,791.46 3839.16,812.7 3847.7,812.7 v1(3850,815) ; U13.E5@3826.56,478.76 3826.56,476.65 3837.81,465.39 v1(3837.81,462.5) ; C3.1@4150.25,1250.07 C3.1@4150.32,1250 4162.7,1237.62 4162.7,1232.3 v1(4165,1230) ; U9.8@4368.9,1130.94 4369.84,1130 v1(4415,1130) ; U11.21@4741.42,1025.83 4741.42,998.58 v1(4750,990) ; U11.41@4830,1140 4839.84,1149.84 U11.5@4839.84,1254.17 ; v1(5515,1105) 5515.55,1105.55 5540.39,1105.55 U8.8@5540.94,1106.1 ; v1(5560,1290) C4.1@5580.32,1290 ; v1(5715,1105) 5715.55,1105.55 5740.39,1105.55 U5.8@5740.94,1106.1 ; U7.3@5774.41,1419.29 5774.7,1419.59 5774.7,1449.7 v1(5775,1450) ; v1(5820,1225) 5820.39,1224.61 5858.66,1224.61 U5.15@5859.06,1224.21 ; v1(5845,1395) 5869.69,1395 C9.1@5870,1394.68 ; U5.10@5859.06,1125.79 5859.59,1126.32 5902.04,1126.32 v1(5902.57,1126.85) 5916.54,1112.88 5919.4,1112.88 5926.18,1106.1 U3.8@5940.94,1106.1 ; U2.3@5874.41,1029.29 5874.7,1029 5874.7,990.3 v1(5875,990) ; U6.8@6140.94,1106.1 6142.29,1107.44 6223.66,1107.44 v1(6225,1108.79)
  Top Layer w8: v1(960,375) D27.2.2@960,400.24 ; D26.2.2@960,827.56 v1(960,845) ; v1(960,1555) v1@965,1555 ; C132.1.2@1142.91,1940 1187.29,1940 1197.29,1950 v1(1200,1950) ; R178.2.1@1233.62,488.9 1235,487.52 v1(1235,465) ; R178.1.1@1233.62,1670 1241.43,1662.19 1255.1,1662.19 1257.29,1660 v1(1260,1660) ; SW2.3@1679.76,113.46 1679.76,149.76 v1(1680,150) ; R107.1@1685,467.72 v1(1685,505) ; v1@1745,508 R108.1@1745,467.72 1745,455 1750,450 1830.31,450 1835,454.69 R106.1@1835,467.72 ; v1(1750,180) 1755,180 C38.1@1790.32,180 1790.32,130.32 v1(1775,115) ; v2(1780,350) 1809.53,379.53 U22.1@1809.53,399.21 ; R105.1@1897.72,390 1900,392.28 1900,404 v1(1903,407) ; SW2.1@1900.24,113.46 1904.17,113.46 1930,139.29 v1(1930,145) ; v1(1950,225) C31.1@1950,250.32 ; v1(2000,75) SW1.4@2050,75 SW1.3@2050,125 SW1.2@2050,175 SW1.1@2050,225 ; R135.1@2110,1016.38 2110,1020.32 2090,1040.32 2090,1082.49 2099.88,1092.37 v1(2100,1092.37) 2100.24,1092.61 2100.24,1115.04 U23.8@2100.47,1115.28 2100.47,1148.41 2122.06,1170 v2(2130,1170) ; R138.1@2280,1513.62 v1(2280,1545) ; v1(2405,2075) 2405,2077.71 2408.82,2081.52 J7.5@2408.82,2125 ; C116.2@2660,1621.26 C116.2@2660,1670.47 ; v1(2715,1700) 2715,1735 2730,1750 R136.1@2776.38,1750 ; v1(2790,745) 2790.94,744.06 2805.94,744.06 U12.Y20@2806.89,743.11 ; U12.Y15@2934.84,743.11 2934.84,744.67 2943.09,752.92 2943.09,758.09 v1(2945,760) ; v1@3060,133.7 3060,108.11 ; v1@3064.69,138.39 U28.4@3112.2,138.39 ; U28.1@3112.2,61.61 3111.4,60.81 3060.81,60.81 3060,60 3060,82.52 ; U28.2@3112.2,87.2 3064.69,87.2 3060,82.52 ; U28.3@3112.2,112.8 3064.69,112.8 3060,108.11 ; U12.Y1@3293.11,743.11 3294.67,743.11 3304.65,753.09 3308.09,753.09 v1(3310,755) ; C2.8.1@4286.77,900 4320.78,900 4321.85,898.93 4326.17,898.93 v2@4327.24,900 ; v2@4334.17,1462.2 4335.24,1463.28 4339.57,1463.28 4340.64,1462.2 C2.7.1@4374.65,1462.2 ; C2.6.1@5271.02,900 5305.03,900 5306.1,898.93 5310.42,898.93 v2@5311.5,900 ; v2@5318.43,1462.2 5319.5,1463.28 5323.82,1463.28 5324.89,1462.2 C2.5.1@5358.9,1462.2 ; C2.3.1@6255.28,900 6289.28,900 6290.35,898.93 6294.68,898.93 v2@6295.75,900 ; v2@6302.68,1462.2 6303.75,1463.28 6308.07,1463.28 6309.15,1462.2 C2.4.1@6343.15,1462.2 ; v2(6826.97,1241.85) 6826.97,1243.19 6856.06,1272.28 R30.2@6860,1272.28 6863.94,1272.28 6869.84,1266.38 R31.1@6900,1266.38 ; v1(6975,980) C14.1@7002.6,980 ; C2.1.1@7239.53,900 7273.53,900 7274.6,898.93 7278.93,898.93 v2@7280,900 ; v2@7286.93,1462.2 7288,1463.28 7292.33,1463.28 7293.4,1462.2 C2.2.1@7327.4,1462.2 ; 3060,82.52 3060,108.11
  Top Layer w10: v1(1380,945) J3.4@1443.5,945 ; v1(1380,1095) J3.10@1443.5,1095 ; v1(1380,1145) J3.12@1443.5,1145 ; v1(1380,1245) J3.16@1443.5,1245 ; v1(1380,1345) J3.20@1443.5,1345 ; v1(1620,380) 1622.28,377.72 R112.1@1622.28,355 ; v1(1710,230) 1712.28,232.28 R111.1@1735,232.28 ; v1@2250,1320 2252.09,1320 2279.17,1292.91 C111.2@2290,1292.91 ; v1(2785,255) 2786.17,256.17 2806.17,256.17 U12.A20@2806.89,256.89 ; v1@2967.22,600.31 v1(2967.22,602.48) ; U20.3@3262.6,914.13 3262.6,870.86 3268.46,865 3375.32,865 C37.1@3390,879.68 ; U12.A1@3293.11,256.89 3293.11,256.28 3303.78,245.61 v1(3303.78,245) ; v1@3685,573.43 v1@3685,574.37 ; v1(5760,1290) C5.1@5780.32,1290 ; C6.1@6099.68,1280 v1(6120,1280)
  GND1 w25: v1(4226.24,588.13) 4268.04,588.13 4333.28,522.89 4394.36,522.89 J1.8.3@4397.24,520 ; J1.7.3@4264.17,1842.2 4267.06,1839.32 4328.14,1839.32 4393.38,1774.08 v1(4435.17,1774.08) ; v1(5210.49,588.13) 5252.29,588.13 5317.53,522.89 5378.61,522.89 J1.6.3@5381.5,520 ; J1.5.3@5248.43,1842.2 5251.31,1839.32 5312.39,1839.32 5377.63,1774.08 v1(5419.43,1774.08) ; v1(6194.75,588.13) 6236.54,588.13 6301.78,522.89 6362.86,522.89 J1.3.3@6365.75,520 ; J1.4.3@6232.68,1842.2 6235.57,1839.32 6296.64,1839.32 6361.88,1774.08 v1(6403.68,1774.08) ; v1(7179,588.13) 7220.8,588.13 7286.03,522.89 7347.11,522.89 J1.1.3@7350,520 ; J1.2.3@7216.93,1842.2 7219.82,1839.32 7280.9,1839.32 7346.13,1774.08 v1(7387.93,1774.08)
  Bottom Layer w6: v1(1575,1965) 1575.2,1964.8 1611.65,1964.8 U30.58@1611.85,1964.61 ; v1(1575,2060) 1575.55,2059.45 1611.49,2059.45 U30.64@1611.85,2059.09 ; v1@1577.36,1917.36 U30.55@1611.85,1917.36 ; U30.48@1611.85,1807.13 1657.13,1807.13 v1(1670,1820) ; v1(1665,2160) 1668.14,2160 1686.65,2141.49 U30.66@1686.65,2118.15 ; C162.1@1675,2239.68 v1(1675,2260) ; R209.2@1800,2243.62 v1(1800,2270) ; v1(1895,1555) 1897.3,1552.7 1897.3,1545.3 1907.13,1535.47 U30.17@1907.13,1511.85 ; U30.80@1907.13,2118.15 1907.13,2157.45 C150.1@1919.68,2170 1919.68,2189.68 v1(1920,2190) ; v1(1995,2160) 1995,2191.81 Y1.2@1996.69,2193.5 ; v1(2015,1560) 2017.36,1557.64 U30.10@2017.36,1511.85 ; Y1.4@2083.31,2256.5 2083.31,2288.31 v1(2085,2290) ; v1(2090,1795) 2095,1795 2098.62,1791.38 U30.114@2218.15,1791.38 ; v1@2350,810 2348.63,811.37 2348.63,816.19 2357.44,825 C32.2@2361.38,825 ; v1(2435,685) 2435,678.62 C29.2@2443.62,670 ; D35.3@2480,2253.31 v1(2480,2280) ; v1(2525,645) R83.1@2545,645 ; v1(2535,800) 2545,790 R84.1@2545,770 ; v3(2545,1890.63) 2548.94,1886.69 U29.3@2583.39,1886.69 ; C63.1@2740.47,475 v1(2765,475) ; v1(2828.34,221.66) 2830,223.33 2830,274.53 C91.1@2865.47,310 ; C95.1@2928.66,440 v1(2940,440) ; v1(3040,770) C100.1@3040,794.53 ; v1(3075,705) 3075,719.53 C75.1@3085,729.53 ; v1(3105,400) 3107.3,402.3 3113.44,402.3 3117.27,406.12 C51.1@3118.88,406.12 ; v1(3160,390) 3163.25,390 3167.12,393.88 3169.77,393.88 3171.02,395.13 3172.62,395.13 C99.1@3173.88,393.88 ; U1.8.16@4251.95,949.84 4280.16,949.84 U1.8.25@4290,940 ; U1.7.25@4360,1415 4362.64,1412.36 U1.7.16@4409.47,1412.36 ; U1.6.16@5236.2,949.84 5301.65,949.84 v2(5311.5,940) ; v2(5318.43,1422.2) 5328.27,1412.36 U1.5.16@5393.72,1412.36 ; v1(5875,990) 5880.32,984.68 C8.1@5880.32,965 ; C7.1@6260,1195.32 6260,1167.14 v1(6291.52,1135.63) ; v2(6302.68,1422.2) 6312.52,1412.36 U1.4.16@6377.97,1412.36 ; v1(7231,1172.21) 7231.1,1172.11 U4.8@7231.1,1100.94
  Bottom Layer w8: v1(735,1550) R191.1.1@768.5,1550 ; v1(735,1600) R176.1.1@776.38,1600 ; v1(735,1670) C138.1.2@776.38,1670 ; v1(735,1710) C141.1.1@780.32,1710 ; v1(735,1830) C136.1.2@776.38,1830 ; v1(735,1870) C139.1.1@780.32,1870 ; v1(735,1940) R192.1.1@768.5,1940 ; v1(735,1990) R177.1.1@776.38,1990 ; v1(740,370) 741.1,368.9 R191.2.1@768.5,368.9 ; v1(740,420) 741.1,418.9 R176.2.1@776.38,418.9 ; v1(740,490) C138.2.2@776.38,490 ; v1(740,530) C141.2.1@780.32,530 ; v1(740,650) 741.1,648.9 C136.2.2@776.38,648.9 ; v1(740,691.1) 741.11,690 C139.2.1@780.32,690 ; v1(740,761.1) 741.1,760 R192.2.1@768.5,760 ; v1(740,811.1) 741.1,810 R177.2.1@776.38,810 ; v1(955,620) 956.1,618.9 U27.2.3@977.13,618.9 U27.2.8@1010,618.9 1028.9,618.9 v1(1030,620) ; v1(955,1720) C128.1.1@970.32,1720 ; v1(955,1800) U27.1.3@977.13,1800 U27.1.8@1010,1800 v1(1030,1800) ; v1(970,555) 970.32,554.68 C128.2.1@970.32,538.89 ; v1(975,1510) 976.91,1511.91 976.91,1516.32 1007.99,1547.4 U26.1.3@1015.87,1547.4 ; U26.2.3@1015.87,366.3 1046.2,366.3 1060,352.5 1060,330 1075,315 1156.42,315 C142.2.1@1170,328.58 1193.58,328.58 v1(1195,330) ; v1(1085,1930) R182.1.1@1116.38,1930 ; v1(1095,750) 1115.28,750 R182.2.1@1116.38,748.9 ; C142.1.1@1170,1509.68 v1(1170,1540) ; C35.2@1720,153.62 1720,157.56 1727.81,165.37 1731.75,165.37 1744.46,178.09 1748.09,178.09 v1(1750,180) ; C39.2@1743.62,380 v1(1770,380) ; v1(1750,320) 1766.38,320 C41.2@1770,323.62 ; U21.3@1774.41,85.71 1774.7,86 1774.7,114.7 v1(1775,115) ; v1(1800,1305) 1818.62,1305 R128.1@1820,1306.38 ; v1(1875,1065) 1902.01,1065 Q11.2@1902.6,1065.59 ; v1(1980,180) C36.1@2000.32,180 ; U16.3@1985.71,275.59 1986.3,275 v1(2015,275) ; R124.1@2060,1143.62 2060,1139.68 2098.09,1101.6 2098.09,1094.28 v1(2100,1092.37) ; C34.1@2080,169.68 2099.68,169.68 v1(2100,170) ; U15.7@2259.06,209.06 2275.94,209.06 v1(2285,200) ; v1(2705,400) 2707.71,400 2710.96,396.75 2728.72,396.75 C44.1@2740.47,385 ; C61.1@2740.47,435 v1(2765,435) ; v1(2850.2,674.21) 2865.32,674.21 C84.1@2875,664.53 ; C143.1@2969.68,60 2975.53,65.85 2978.34,65.85 2989.65,77.16 2998,85.51 2998,123 3015,140 v1(3060,140) 3123.62,76.38 R142.1@3200,76.38 R143.1@3250,76.38 ; v1(3005,705) 3007.71,705 3011.23,708.53 3024.87,708.53 C122.1@3025,708.66 ; C119.1@3410,1570 v1(3430,1570) ; R144.1@3413.62,335 v1(3440,335) ; R133.1@3640,1276.38 3638.62,1275 3620,1275 3615,1280 3615,1345 3620,1350 3640,1350 3650,1360 3650,1386.02 U25.2@3652.8,1388.82 3652.8,1422.2 v1(3650,1425) ; R132.1@3650,1593.62 v1(3650,1625) ; v1(4144.17,1472.2) R1.7.1@4175.42,1472.2 ; v1(4144.17,1512.2) R2.7.1@4170.55,1512.2 ; U1.8.10@4317.4,864.7 4317.4,890.85 4321.55,895 U1.8.25@4327.24,895 ; U1.7.25@4334.17,1467.2 4339.87,1467.2 4344.02,1471.35 U1.7.10@4344.02,1497.5 ; R1.8.1@4485.99,890 v1(4517.24,890) ; R2.8.1@4490.87,850 v1(4517.24,850) ; v1(5128.43,1472.2) R1.5.1@5159.68,1472.2 ; v1(5128.43,1512.2) R2.5.1@5154.8,1512.2 ; U1.6.10@5301.65,864.7 5301.65,890.85 5305.8,895 U1.6.25@5311.5,895 ; U1.5.25@5318.43,1467.2 5324.12,1467.2 5328.27,1471.35 U1.5.10@5328.27,1497.5 ; R1.6.1@5470.25,890 v1(5501.5,890) ; R2.6.1@5475.12,850 v1(5501.5,850) ; v1(6110,1485) 6129.42,1485 6142.21,1472.2 R1.4.1@6143.93,1472.2 ; v1(6112.68,1512.2) R2.4.1@6139.06,1512.2 ; U1.3.10@6285.91,864.7 6285.91,890.85 6290.06,895 U1.3.25@6295.75,895 ; U1.4.25@6302.68,1467.2 6308.37,1467.2 6312.52,1471.35 U1.4.10@6312.52,1497.5 ; R1.3.1@6454.5,890 v1(6485.75,890) ; R2.3.1@6459.37,850 v1(6485.75,850) ; v1(7096.93,1472.2) R1.2.1@7128.18,1472.2 ; v1(7096.93,1512.2) R2.2.1@7123.31,1512.2 ; U1.1.16@7204.7,949.84 7230.85,949.84 7235,945.69 U1.1.25@7235,945 ; U1.1.10@7270.16,864.7 7270.16,890.85 7274.31,895 U1.1.25@7280,895 ; U1.2.25@7286.93,1467.2 7292.62,1467.2 7296.77,1471.35 U1.2.10@7296.77,1497.5 ; R1.1.1@7438.75,890 v1(7470,890) ; R2.1.1@7443.62,850 v1(7470,850)
  Bottom Layer w10: U17.3@2205.87,897.4 2213.74,897.4 2240.32,923.98 C33.1@2240.32,950 v1(2215,950) ; C28.2@2260,783.62 2286.46,783.62 2292.84,790 v1(2295,790) ; v1(3515,585) 3525,575 R62.1@3545,575 3545,578.97 3547.5,581.47 3559.24,581.47 3580.77,603 3582.5,603 3585,605.5 R61.1@3585,610 ; C27.2@3677.81,562.5 3680.97,562.5 3683.47,565 3683.47,573.47 v1(3685,575) ; v1(3756.6,589.87) 3756.6,560.22 C25.2@3756.38,560 3760.31,560 C25.2@3767.13,566.81 ; v1(3837.81,462.5) 3837.81,446.81 3844.63,440 C26.2@3845,440 ; U18.3@3847.6,545.87 3847.6,553.74 3869.43,575.57 ; v1(3850,690) 3870.63,690 3873.13,687.5 3873.13,578.13 3870,575 ; U1.3.16@6220.45,949.84 6269.84,949.84 U1.3.25@6270,950 ; U10.21@6711.42,1284.17 6711.42,1258.58 U10.41@6735,1235 ; U10.41@6800,1170 6809.84,1160.16 U10.5@6809.84,1055.83 ; U1.2.25@7310,1415 7312.64,1412.36 U1.2.16@7362.22,1412.36 ; C10.1@7365,1309.68 v1(7365,1330)
  Bottom Layer w25: RV3.8.1@4207.24,561.46 4207.24,570 4216.31,579.06 4217.18,579.06 v1(4226.24,588.13) ; v1(4435.17,1774.08) 4444.24,1783.14 4445.11,1783.14 4454.17,1792.2 RV3.7.1@4454.17,1800.75 ; RV3.6.1@5191.5,561.46 5191.5,570 5200.56,579.06 5201.43,579.06 v1(5210.49,588.13) ; v1(5419.43,1774.08) 5428.49,1783.14 5429.36,1783.14 5438.43,1792.2 RV3.5.1@5438.43,1800.75 ; RV3.3.1@6175.75,561.46 6175.75,570 6184.81,579.06 6185.68,579.06 v1(6194.75,588.13) ; v1(6403.68,1774.08) 6412.74,1783.14 6413.61,1783.14 6422.68,1792.2 RV3.4.1@6422.68,1800.75 ; RV3.1.1@7160,561.46 7160,570 7169.06,579.06 7169.94,579.06 v1(7179,588.13) ; v1(7387.93,1774.08) 7396.99,1783.14 7397.87,1783.14 7406.93,1792.2 RV3.2.1@7406.93,1800.75
  other v1: 1600,40 4730,40 4770,40 4810,40 4850,40 4890,40 5720,40 5760,40 5800,40 5840,40 5880,40 6760,40 6800,40 6840,40 6880,40 6920,40 1600,80 2600,80 1600,120 2600,120 880,150 920,150 960,150 1000,150 1040,150 1600,160 2600,160 1600,200 2600,200 2600,240 1750,350 3245,435 7800,440 7800,480 660,490 1745,510 660,515 7800,520 660,540 7800,560 660,565 660,590 7800,600 660,615 660,640 660,665 660,690 3135,760 4192.24,780 5176.5,780 6160.75,780 7145,780 4192.24,800 5176.5,800 6160.75,800 7145,800 4192.24,820 5176.5,820 6160.75,820 7145,820 6600,940 6630,940 4660,960 5000,960 6975,960 6630,965 4660,980 5000,980 4660,1000 5000,1000 6975,1000 1290,1040 660,1080 1290,1080 840,1100 660,1105 1290,1120 660,1130 840,1140 660,1155 1290,1160 660,1180 840,1180 1290,1200 2215,1200 2260,1200 2305,1200 2340,1200 2380,1200 2420,1200 660,1205 840,1220 660,1230 2320,1235 660,1255 840,1260 2335,1260 2430,1260 1755,1265 1795,1270 660,1280 2250,1325 2335,1325 2430,1325 5010,1341.41 5035,1341.41 4670,1360 6630,1360 6970,1360 4670,1380 6630,1380 6970,1380 4670,1400 6630,1400 6970,1400 7800,1450 7800,1490 7800,1530 4469.17,1542.2 5453.43,1542.2 6437.68,1542.2 7421.93,1542.2 2715,1550 4469.17,1562.2 5453.43,1562.2 6437.68,1562.2 7421.93,1562.2 7800,1570 2715,1575 4469.17,1582.2 5453.43,1582.2 6437.68,1582.2 7421.93,1582.2 2715,1600 3520,1600 3540,1600 3560,1600 7800,1610 2715,1625 2715,1650 660,1671.79 2715,1675 660,1696.79 660,1721.79 660,1746.79 660,1771.79 660,1796.79 660,1821.79 660,1846.79 660,1871.79 3830,1900 1575,1917.36 3830,1940 3830,1980 3830,2020 3830,2060 2680,2130 1430,2140 2680,2175 1430,2180 1430,2220 2680,2220 1430,2260 2680,2260 800,2300 840,2300 880,2300 920,2300 960,2300 1430,2300 2700,2300 4740,2320 4780,2320 4820,2320 4860,2320 4900,2320 5830,2320 5870,2320 5910,2320 5950,2320 5990,2320 6730,2320 6770,2320 6810,2320 6850,2320 6890,2320
  other v2: 1150,567.4 1118.5,598.9 1150,598.9 1181.5,598.9 1150,630.39 4327.24,896.69 5311.5,896.69 6295.75,896.69 7280,896.69 4283.94,940 4327.24,940 4370.55,940 5268.19,940 5354.8,940 6252.44,940 6295.75,940 6339.06,940 7236.69,940 7280,940 7323.31,940 4327.24,983.31 5311.5,983.31 6295.75,983.31 7280,983.31 4803.03,1068.15 4856.97,1068.15 6773.03,1098.15 6826.97,1098.15 4758.15,1113.03 4803.03,1113.03 4856.97,1113.03 4901.85,1113.03 6728.15,1143.03 6773.03,1143.03 6826.97,1143.03 6871.85,1143.03 4758.15,1166.97 4803.03,1166.97 4856.97,1166.97 4901.85,1166.97 2090.63,1170 2169.37,1170 6728.15,1196.97 6773.03,1196.97 6826.97,1196.97 6871.85,1196.97 4803.03,1211.85 4856.97,1211.85 6773.03,1241.85 4334.17,1378.9 5318.43,1378.9 6302.68,1378.9 7286.93,1378.9 4290.87,1422.2 4334.17,1422.2 4377.48,1422.2 5275.12,1422.2 5361.73,1422.2 6259.37,1422.2 6345.98,1422.2 7243.62,1422.2 7286.93,1422.2 7330.24,1422.2 4334.17,1465.51 5318.43,1465.51 6302.68,1465.51 7286.93,1465.51 1150,1748.5 1118.5,1780 1150,1780 1181.5,1780 1150,1811.5
  other v3: 4415.59,430 4458.9,430 5399.84,430 5443.15,430 6384.09,430 6427.4,430 7368.35,430 7411.65,430 4202.52,1932.2 4245.83,1932.2 5186.77,1932.2 5230.08,1932.2 6171.02,1932.2 6214.33,1932.2 7155.28,1932.2 7198.58,1932.2 2545,1933.94
HSS_C\S\: U10.10 U11.10 U12.B1 | length 5843.2
  Top Layer w4: U12.B1@3293.11,282.48 3280,269.37 3280,216.96 3431.96,65 3434.12,65 3435.12,64 3909.76,64 3962.76,117 4044.53,117 4096.53,169 4681,169 v1(4730,120) 4779,169 5057.94,169 5074.94,186 5478.06,186 5509.06,155 5600,155 5655,210 5927.79,210 5973.79,164 5987.37,164 6015.37,192 6608,192 6640,160 6700,160 v1(6720,180) ; v1(4730,1290) 4741.42,1278.58 U11.10@4741.42,1254.17
  Bottom Layer w4: v1(4730,120) v1(4730,1290) ; U10.10@6711.42,1055.83 6711.42,189.32 6720,180.73 v1(6720,180)
IO_EN1: U1.1.3 U12.A18 | length 5751.4
  Top Layer w4: U12.A18@2858.07,256.89 2870,244.96 v1(2870,225)
  Layer 2 w4: v1(2870,225) 2905,190 2913,182 2913,154.63 3011.63,56 3941,56 3961,76 4075.21,76 4089.21,62 4109.53,62 4200.53,153 4944.31,153 4977.31,186 5478.31,186 5517.31,225 5577.44,225 5616.44,186 5951.79,186 5973.79,164 6010.49,164 6040.49,194 6614.79,194 6643.79,165 6745,165 6774,194 7303.66,194 7312.66,185 v1(7315,185)
  Bottom Layer w4: v1(7315,185) 7315,223.94 7543,451.94 7543,932 7525.16,949.84 U1.1.3@7355.3,949.84
IO_EN2: U1.2.3 U12.A13 U15.8 | length 7242.8
  Top Layer w4: U12.A13@2986.02,256.89 2986.02,217.02 2999.17,203.87 2999.17,115.83 v1(3015,100) ; v1(7170,1420) 7156.92,1406.92 7156.92,1379.39 7242.31,1294 7471,1294 7490,1275 v1(7490,1265)
  Layer 2 w4: v1(3015,100) 3017.21,97.79 3026,97.79 3036.79,87 3046.69,87 3053.69,80 3931.06,80 3951.06,100 4111.31,100 4180.31,169 4926.63,169 4998.63,241 5044,241 5091,194 5475,194 5514,233 5580.75,233 5619.75,194 6029.18,194 6037.18,202 7319.21,202 7326.21,195 7410,195 v1(7420,205)
  Bottom Layer w4: U15.8@2259.06,90.94 2259.06,60.94 2275,45 2785,45 2790,40 2983.69,40 3015,71.31 v1(3015,100) ; v1(7170,1420) 7173.79,1420 7181.43,1412.36 U1.2.3@7211.63,1412.36 ; v1(7420,205) 7442,227 7442,259.57 7608,425.57 7608,871.31 7638,901.31 7638,952.1 7483,1107.1 7483,1231.79 7491.13,1239.92 7491.13,1252.34 7490.84,1252.63 7490.84,1264.16 v1(7490,1265)
IO_EN3: U1.3.3 U12.U1 | length 6030.2
  Top Layer w4: U12.U1@3293.11,666.34 3321.34,666.34 3340,685 3418.69,685 3675.69,942 3917,942 v1(3955,980) ; v1(3880,2170) 3901,2149 6073.63,2149 6087.63,2135 v1(6500,2135) ; v1(6400,950) 6440,950 v1(6455,965)
  Bottom Layer w4: v1(3880,2170) 3950,2100 3950,1276.31 3927,1253.31 3927,1078 3955,1050 v1(3955,980) ; U1.3.3@6371.04,949.84 6371.12,949.92 6399.92,949.92 v1(6400,950) ; v1(6455,965) 6455,1300 6485,1330 6545,1330 6560,1345 6560,2075 v1(6500,2135)
IO_EN4: U1.4.3 U12.T1 | length 5253.3
  Top Layer w4: U12.T1@3293.11,640.75 3331.91,640.75 3342.16,651 3367.84,651 3374.84,644 3389,644 3675,930 3679,934 3939,934 v1(3955,950) ; v1(3900,2210) 3900,2173.79 3916.79,2157 6095.66,2157 6102.66,2150 v1(6105,2150)
  Bottom Layer w4: v1(3900,2210) 3900,2171.21 3912,2159.21 3912,2153 3958,2107 3958,1273 3935,1250 3935,1081.31 3971,1045.31 3971,966 v1(3955,950) ; v1(6105,2150) 6105,2127.47 6036,2058.47 6036,1525.47 6149.11,1412.36 U1.4.3@6227.38,1412.36
IO_EN5: U1.5.3 U12.A16 | length 3480.7
  Top Layer w4: U12.A16@2909.25,256.89 2909.25,239.54 2923.79,225 v1(2925,225)
  Layer 2 w4: v1(2925,225) 2989.36,225 3017.36,197 3092.27,197 3095.27,194 3196,194 3207,183 3207,175.47 3225.47,157 3252.49,157 3280.49,129 3910.31,129 3975.31,194 4899,194 v1(4940,235)
  Bottom Layer w4: v1(4940,235) 4982,277 4982,808.31 5170,996.31 5170,1400 5182.36,1412.36 U1.5.3@5243.13,1412.36
IO_EN6: U1.6.3 U12.C3 | length 3456.7
  Top Layer w4: U12.C3@3241.93,308.07 3255,295 3270,295 3305,295 3318.28,281.72 3318.28,190 3433.28,75 3435.43,75 3438.43,72 3906.45,72 3959.45,125 4041.21,125 4093.21,177 5054.63,177 5071.63,194 5501,194 v1(5525,170)
  Top Layer w6: U12.C3@3241.93,308.07 U12.C3@3241.93,310.18
  Bottom Layer w4: U1.6.3@5386.79,949.84 5525.16,949.84 5575,900 5575,295 5525,245 v1(5525,170)
IO_EN7: U1.7.3 U12.D8 | length 2671.4
  Top Layer w4: v1(3110,315) 3112.11,317.11 3112.11,331.79 U12.D8@3113.98,333.66 ; v1(4065,1420) v1(4200,1420)
  Layer 2 w4: v1(3115,162) 3117,160 3199.85,160 3210.85,149 3218.85,141 3245.86,141 3273.86,113 3918.8,113 3939.71,133.91 4030.12,133.91 4055,158.79 v1(4055,160)
  Bottom Layer w4: v1(3110,315) 3110,256.09 3094.42,240.51 3094.42,240 3094.42,195.58 3115,175 v1(3115,162) ; v1(4055,160) 4005,210 4005,852.37 4031,878.37 4031,1051 4065,1085 v1(4065,1420) ; v1(4200,1420) 4213.79,1420 4221.43,1412.36 U1.7.3@4258.88,1412.36
IO_EN8: U1.8.3 U12.A3 | length 2307.4
  Top Layer w4: v1(3230,185) 3230,185.07 3241.93,197 U12.A3@3241.93,256.89
  Layer 2 w4: v1(3230,185) 3247.12,185 3287.12,145 3890,145 3955,210 4535,210 4555,230 v1(4555,265)
  Bottom Layer w4: U1.8.3@4402.54,949.84 4485.16,949.84 4582,853 4582,338.21 4555,311.21 v1(4555,265)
